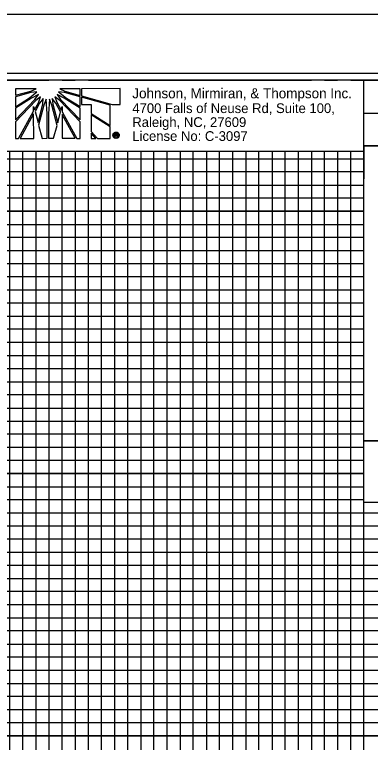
# Model space of a CAD drawing. Extents: x 1648435 to 1651603, y 802691 to 845762.
# Drawn here: x 1650196.2 to 1650331.8, y 803513.5 to 803791 of the extents above; entities that cross this region are included whole.
import ezdxf

# ---------------------------------------------------------------- set-up
doc = ezdxf.new("R2010")
doc.units = 0
for name, color, linetype in [('Prop Dimension Text', 7, 'Continuous'), ('Sheet Cutting Line CELL', 7, 'Continuous'), ('Sheet DOT Grid CELL', 7, 'Continuous'), ('Sheet Plan CELL', 7, 'Continuous'), ('Sheet Plot Border Inside CELL', 7, 'Continuous'), ('Sheet Plot Border Outside CELL', 7, 'Continuous'), ('Sheet Profile CELL', 7, 'Continuous'), ('Sheet Profile Grid Major CELL', 7, 'Continuous'), ('Sheet Profile Grid Middle CELL', 7, 'Continuous'), ('Sheet Profile Grid Minor CELL', 7, 'Continuous'), ('Sheet Sticker Exception Certification CELL', 7, 'Continuous')]:
    doc.layers.add(name, color=color, linetype=linetype)

msp = doc.modelspace()

# ---------------------------------------------------------------- linework, layer by layer
at = {"layer": 'Prop Dimension Text'}
for p, q in [((1650204.41, 803762.75), (1650196.52, 803762.75)), ((1650196.52, 803762.75), (1650196.52, 803760.23)), ((1650202.4, 803761.86), (1650204.41, 803762.75)), ((1650221.14, 803762.73), (1650213.35, 803762.76)), ((1650213.35, 803762.76), (1650215.32, 803761.84)), ((1650221.14, 803760.21), (1650221.14, 803762.73)), ((1650236.43, 803762.78), (1650221.68, 803762.77)), ((1650221.68, 803762.77), (1650221.68, 803760.06)), ((1650236.44, 803756.74), (1650236.43, 803762.78)), ((1650196.52, 803760.23), (1650202.4, 803761.86)), ((1650202.4, 803761.31), (1650196.52, 803759.69)), ((1650196.52, 803759.69), (1650196.52, 803755.89)), ((1650201.79, 803759.23), (1650204.69, 803761.59)), ((1650204.69, 803761.59), (1650202.4, 803761.31)), ((1650205.27, 803760.51), (1650202.6, 803759.15)), ((1650203.92, 803758.61), (1650205.27, 803760.51)), ((1650206.08, 803759.66), (1650204.22, 803758.22)), ((1650205.23, 803757.42), (1650206.08, 803759.66)), ((1650211.53, 803759.67), (1650212.39, 803757.42)), ((1650213.39, 803758.23), (1650211.53, 803759.67)), ((1650212.35, 803760.51), (1650213.71, 803758.58)), ((1650215.06, 803759.16), (1650212.35, 803760.51)), ((1650212.96, 803761.6), (1650215.9, 803759.2)), ((1650215.13, 803761.33), (1650212.96, 803761.6)), ((1650221.14, 803759.68), (1650215.13, 803761.33)), ((1650215.32, 803761.84), (1650221.14, 803760.21)), ((1650221.1, 803755.96), (1650221.14, 803759.68)), ((1650221.68, 803760.06), (1650221.68, 803759.98)), ((1650221.68, 803759.98), (1650233.3, 803756.74)), ((1650221.68, 803759.56), (1650221.68, 803759.52)), ((1650232.56, 803756.47), (1650221.68, 803759.56)), ((1650221.68, 803759.52), (1650221.69, 803756.69)), ((1650196.52, 803755.89), (1650201.79, 803759.23)), ((1650202.6, 803759.15), (1650196.52, 803755.28)), ((1650196.53, 803750.9), (1650203.92, 803758.61)), ((1650204.22, 803758.22), (1650196.53, 803750.16)), ((1650203.76, 803754.74), (1650205.23, 803757.42)), ((1650205.7, 803757.25), (1650203.96, 803754.08)), ((1650205.09, 803749.87), (1650206.9, 803756.87)), ((1650207.09, 803759.04), (1650205.7, 803757.25)), ((1650206.9, 803756.87), (1650207.09, 803759.04)), ((1650208.25, 803758.73), (1650207.29, 803756.48)), ((1650208.56, 803753.19), (1650208.25, 803758.73)), ((1650209.41, 803758.73), (1650209.05, 803753.19)), ((1650210.34, 803756.48), (1650209.41, 803758.73)), ((1650210.53, 803759.04), (1650210.77, 803756.8)), ((1650211.89, 803757.26), (1650210.53, 803759.04)), ((1650210.77, 803756.8), (1650212.59, 803749.71)), ((1650213.71, 803753.97), (1650211.89, 803757.26)), ((1650212.39, 803757.42), (1650213.89, 803754.63)), ((1650221.1, 803750.11), (1650213.39, 803758.23)), ((1650213.71, 803758.58), (1650221.1, 803750.84)), ((1650221.1, 803755.33), (1650215.06, 803759.16)), ((1650215.9, 803759.2), (1650221.1, 803755.96)), ((1650221.69, 803756.69), (1650225.29, 803756.69)), ((1650225.29, 803756.69), (1650225.29, 803753.32)), ((1650233.3, 803756.74), (1650236.44, 803756.74)), ((1650196.52, 803755.28), (1650196.53, 803750.9)), ((1650197.69, 803743.79), (1650203.41, 803754.16)), ((1650203.41, 803754.16), (1650203.41, 803756.01)), ((1650203.41, 803756.01), (1650203.76, 803754.74)), ((1650203.96, 803754.08), (1650205.09, 803749.87)), ((1650207.29, 803756.48), (1650205.32, 803748.89)), ((1650212.36, 803748.78), (1650210.34, 803756.48)), ((1650212.59, 803749.71), (1650213.71, 803753.97)), ((1650213.89, 803754.63), (1650214.25, 803756.02)), ((1650214.25, 803756.02), (1650214.25, 803753.97)), ((1650214.25, 803753.97), (1650219.87, 803743.81)), ((1650221.1, 803750.84), (1650221.1, 803755.33)), ((1650232.57, 803748.72), (1650232.56, 803756.47)), ((1650203.42, 803753.15), (1650198.24, 803743.79)), ((1650203.47, 803743.8), (1650203.42, 803753.15)), ((1650208.57, 803743.84), (1650208.56, 803753.19)), ((1650209.05, 803753.19), (1650209.06, 803743.84)), ((1650219.29, 803743.85), (1650214.25, 803752.97)), ((1650214.25, 803752.97), (1650214.26, 803743.84)), ((1650225.29, 803753.32), (1650232.57, 803748.72)), ((1650225.29, 803752.74), (1650225.3, 803746.47)), ((1650232.57, 803748.18), (1650225.29, 803752.74)), ((1650196.53, 803750.16), (1650196.53, 803743.79)), ((1650205.32, 803748.89), (1650206.64, 803743.83)), ((1650211.01, 803743.84), (1650212.36, 803748.78)), ((1650221.11, 803743.81), (1650221.1, 803750.11)), ((1650225.3, 803746.47), (1650227.81, 803743.82)), ((1650227.12, 803743.82), (1650225.3, 803745.78)), ((1650225.3, 803745.78), (1650225.3, 803743.82)), ((1650232.57, 803743.82), (1650232.57, 803748.18)), ((1650234.42, 803744.49), (1650234.42, 803745.56)), ((1650234.42, 803745.56), (1650234.86, 803745.56)), ((1650234.86, 803746.19), (1650234.86, 803745.97)), ((1650234.86, 803745.97), (1650234.86, 803746.19)), ((1650234.86, 803745.56), (1650234.86, 803745.36)), ((1650234.86, 803745.36), (1650234.86, 803745.56)), ((1650234.86, 803745.56), (1650234.92, 803745.56)), ((1650196.53, 803743.79), (1650197.69, 803743.79)), ((1650198.24, 803743.79), (1650203.47, 803743.8)), ((1650206.64, 803743.83), (1650208.57, 803743.84)), ((1650209.06, 803743.84), (1650211.01, 803743.84)), ((1650214.26, 803743.84), (1650219.29, 803743.85)), ((1650219.87, 803743.81), (1650221.11, 803743.81)), ((1650225.3, 803743.82), (1650227.12, 803743.82)), ((1650227.81, 803743.82), (1650232.57, 803743.82)), ((1650234.66, 803744.49), (1650234.42, 803744.49)), ((1650234.86, 803745.36), (1650234.66, 803745.36)), ((1650234.66, 803745.36), (1650234.66, 803745.1)), ((1650234.66, 803745.1), (1650234.86, 803745.1)), ((1650234.86, 803744.91), (1650234.66, 803744.91)), ((1650234.66, 803744.91), (1650234.66, 803744.49)), ((1650234.89, 803745.36), (1650234.86, 803745.36)), ((1650234.86, 803745.1), (1650234.86, 803744.91)), ((1650234.86, 803744.91), (1650234.86, 803745.1)), ((1650234.86, 803745.1), (1650234.87, 803745.1)), ((1650234.87, 803744.91), (1650234.86, 803744.91)), ((1650234.86, 803744.07), (1650234.86, 803743.83)), ((1650234.86, 803743.83), (1650234.86, 803744.07)), ((1650234.86, 803744.07), (1650234.87, 803744.07)), ((1650234.87, 803743.83), (1650234.86, 803743.83))]:
    msp.add_line(p, q, dxfattribs=at)
msp.add_lwpolyline([(1650179.28, 803738.96), (1650329.23, 803738.96), (1650329.23, 803766.02), (1650179.28, 803766.02)], close=True, dxfattribs=at)
for points in [[(1650202.4, 803761.86), (1650204.41, 803762.75), (1650196.52, 803762.75), (1650196.52, 803760.23), (1650202.4, 803761.86)], [(1650215.32, 803761.84), (1650221.14, 803760.21), (1650221.14, 803762.73), (1650213.35, 803762.76), (1650215.32, 803761.84)], [(1650236.43, 803762.78), (1650221.68, 803762.77), (1650221.68, 803760.06), (1650221.68, 803759.98), (1650233.3, 803756.74), (1650236.44, 803756.74), (1650236.43, 803762.78)], [(1650196.52, 803759.69), (1650196.52, 803755.89), (1650201.79, 803759.23), (1650204.69, 803761.59), (1650202.4, 803761.31), (1650196.52, 803759.69)], [(1650196.52, 803755.28), (1650196.53, 803750.9), (1650203.92, 803758.61), (1650205.27, 803760.51), (1650202.6, 803759.15), (1650196.52, 803755.28)], [(1650206.08, 803759.66), (1650204.22, 803758.22), (1650196.53, 803750.16), (1650196.53, 803743.79), (1650197.69, 803743.79), (1650203.41, 803754.16), (1650203.41, 803756.01), (1650203.76, 803754.74), (1650205.23, 803757.42), (1650206.08, 803759.66)], [(1650211.53, 803759.67), (1650212.39, 803757.42), (1650213.89, 803754.63), (1650214.25, 803756.02), (1650214.25, 803753.97), (1650219.87, 803743.81), (1650221.11, 803743.81), (1650221.1, 803750.11), (1650213.39, 803758.23), (1650211.53, 803759.67)], [(1650212.35, 803760.51), (1650213.71, 803758.58), (1650221.1, 803750.84), (1650221.1, 803755.33), (1650215.06, 803759.16), (1650212.35, 803760.51)], [(1650212.96, 803761.6), (1650215.9, 803759.2), (1650221.1, 803755.96), (1650221.14, 803759.68), (1650215.13, 803761.33), (1650212.96, 803761.6)], [(1650221.68, 803759.56), (1650221.68, 803759.52), (1650221.69, 803756.69), (1650225.29, 803756.69), (1650225.29, 803753.32), (1650232.57, 803748.72), (1650232.56, 803756.47), (1650221.68, 803759.56)], [(1650207.09, 803759.04), (1650205.7, 803757.25), (1650203.96, 803754.08), (1650205.09, 803749.87), (1650206.9, 803756.87), (1650207.09, 803759.04)], [(1650207.29, 803756.48), (1650205.32, 803748.89), (1650206.64, 803743.83), (1650208.57, 803743.84), (1650208.56, 803753.19), (1650208.25, 803758.73), (1650207.29, 803756.48)], [(1650209.41, 803758.73), (1650209.05, 803753.19), (1650209.06, 803743.84), (1650211.01, 803743.84), (1650212.36, 803748.78), (1650210.34, 803756.48), (1650209.41, 803758.73)], [(1650210.53, 803759.04), (1650210.77, 803756.8), (1650212.59, 803749.71), (1650213.71, 803753.97), (1650211.89, 803757.26), (1650210.53, 803759.04)], [(1650198.24, 803743.79), (1650203.47, 803743.8), (1650203.42, 803753.15), (1650198.24, 803743.79)], [(1650214.26, 803743.84), (1650219.29, 803743.85), (1650214.25, 803752.97), (1650214.26, 803743.84)], [(1650225.29, 803752.74), (1650225.3, 803746.47), (1650227.81, 803743.82), (1650232.57, 803743.82), (1650232.57, 803748.18), (1650225.29, 803752.74), (1650225.29, 803752.74)], [(1650225.3, 803743.82), (1650225.3, 803743.82), (1650227.12, 803743.82), (1650225.3, 803745.78), (1650225.3, 803743.82)], [(1650235.33, 803744.74), (1650235.33, 803744.68), (1650235.33, 803744.64), (1650235.33, 803744.61), (1650235.36, 803744.49), (1650235.14, 803744.49)]]:
    msp.add_lwpolyline(points, dxfattribs=at)
for points, degree in [([(1650234.86, 803743.83), (1650234.54, 803743.83), (1650234.25, 803743.95), (1650234.02, 803744.18), (1650233.78, 803744.41), (1650233.67, 803744.69), (1650233.67, 803745.02), (1650233.67, 803745.35), (1650233.78, 803745.64), (1650234.02, 803745.85), (1650234.25, 803746.08), (1650234.52, 803746.19), (1650234.86, 803746.19)], 3), ([(1650234.86, 803745.97), (1650234.59, 803745.97), (1650234.37, 803745.88), (1650234.18, 803745.71), (1650234, 803745.52), (1650233.9, 803745.29), (1650233.9, 803745.02), (1650233.9, 803744.76), (1650234, 803744.53), (1650234.18, 803744.34), (1650234.37, 803744.16), (1650234.59, 803744.07), (1650234.86, 803744.07)], 3), ([(1650234.86, 803746.19), (1650235.19, 803746.19), (1650235.47, 803746.08), (1650235.7, 803745.85), (1650235.94, 803745.64), (1650236.06, 803745.36), (1650236.06, 803745.03)], 3), ([(1650234.87, 803744.07), (1650235.13, 803744.07), (1650235.35, 803744.16), (1650235.54, 803744.34), (1650235.72, 803744.53), (1650235.82, 803744.76), (1650235.82, 803745.03), (1650235.82, 803745.29), (1650235.72, 803745.52), (1650235.54, 803745.71), (1650235.35, 803745.88), (1650235.13, 803745.97), (1650234.86, 803745.97)], 3), ([(1650234.92, 803745.56), (1650235.2, 803745.56), (1650235.33, 803745.45), (1650235.33, 803745.24), (1650235.33, 803745.14), (1650235.3, 803745.06), (1650235.21, 803745)], 3), ([(1650234.87, 803745.1), (1650235.02, 803745.1), (1650235.1, 803745.15), (1650235.1, 803745.24), (1650235.1, 803745.32), (1650235.03, 803745.36), (1650234.89, 803745.36)], 3), ([(1650236.06, 803745.03), (1650236.06, 803744.69), (1650235.94, 803744.41), (1650235.72, 803744.18), (1650235.48, 803743.95), (1650235.2, 803743.83), (1650234.87, 803743.83)], 3), ([(1650235.05, 803744.87), (1650235.02, 803744.89), (1650234.96, 803744.91), (1650234.87, 803744.91)], 2), ([(1650235.14, 803744.49), (1650235.11, 803744.55), (1650235.09, 803744.61), (1650235.09, 803744.68), (1650235.09, 803744.78), (1650235.08, 803744.84), (1650235.05, 803744.87)], 3), ([(1650235.21, 803745), (1650235.28, 803744.97), (1650235.32, 803744.88), (1650235.33, 803744.74)], 2)]:
    msp.add_open_spline(points, degree=degree, dxfattribs=at)
at = {"layer": 'Sheet Cutting Line CELL'}
msp.add_line((1650546.28, 803791.02), (1648862.28, 803791.02), dxfattribs=at)
at = {"layer": 'Sheet DOT Grid CELL'}
for p, q in [((1650229.28, 803266.02), (1650229.28, 803718.48)), ((1650279.28, 803266.02), (1650279.28, 803718.48)), ((1650329.23, 803716.02), (1649029.28, 803716.02)), ((1650329.23, 803666.02), (1649029.28, 803666.02)), ((1650329.28, 803266.02), (1650329.28, 803628.47)), ((1650329.28, 803616.02), (1649029.28, 803616.02)), ((1650529.28, 803566.02), (1649029.28, 803566.02)), ((1650529.28, 803516.02), (1649029.28, 803516.02))]:
    msp.add_line(p, q, dxfattribs=at)
at = {"layer": 'Sheet Plan CELL'}
msp.add_line((1650329.23, 803740.94), (1650329.23, 803728.45), dxfattribs=at)
msp.add_line((1650329.23, 803740.94), (1650329.23, 803728.45), dxfattribs=at)
msp.add_line((1650329.23, 803740.94), (1650329.23, 803728.45), dxfattribs=at)
at = {"layer": 'Sheet Plot Border Inside CELL'}
msp.add_lwpolyline([(1648875.28, 802713.47), (1650541.78, 802713.47), (1650541.78, 803768.57), (1648875.28, 803768.57)], close=True, dxfattribs=at)
at = {"layer": 'Sheet Plot Border Outside CELL'}
msp.add_lwpolyline([(1648862.28, 802691.02), (1650546.28, 802691.02), (1650546.28, 803791.02), (1648862.28, 803791.02)], close=True, dxfattribs=at)
at = {"layer": 'Sheet Profile CELL'}
msp.add_line((1650329.23, 803753.47), (1650529.28, 803753.47), dxfattribs=at)
for points in [[(1650529.28, 803766.02), (1649029.28, 803766.02), (1649029.28, 802716.02), (1650529.28, 802716.02)], [(1650329.23, 803766.02), (1650529.28, 803766.02), (1650529.28, 803740.97), (1650329.23, 803740.97)], [(1650329.23, 803740.97), (1650429.28, 803740.97), (1650429.28, 803628.47), (1650329.23, 803628.47)]]:
    msp.add_lwpolyline(points, close=True, dxfattribs=at)
at = {"layer": 'Sheet Profile Grid Major CELL'}
for points in [[(1650029.28, 803766.02), (1650079.28, 803766.02), (1650079.28, 803266.02), (1650129.28, 803266.02), (1650129.28, 803766.02), (1650179.28, 803766.02), (1650179.28, 803266.02), (1650229.28, 803266.02), (1650229.28, 803738.96)], [(1650229.28, 803766.02), (1650279.28, 803766.02)], [(1650279.23, 803738.96), (1650279.23, 803266.02), (1650329.23, 803266.02), (1650329.23, 803766.02), (1650355.53, 803766.02)], [(1649029.28, 803716.02), (1650329.28, 803716.02)], [(1650329.28, 803666.02), (1649029.28, 803666.02), (1649029.28, 803616.02), (1650329.28, 803616.02)], [(1650529.28, 803566.02), (1649029.28, 803566.02), (1649029.28, 803516.02), (1650529.28, 803516.02)]]:
    msp.add_lwpolyline(points, dxfattribs=at)
at = {"layer": 'Sheet Profile Grid Middle CELL'}
for points in [[(1650004.28, 803266.02), (1650054.28, 803266.02), (1650054.28, 803766.02), (1650104.28, 803766.02), (1650104.28, 803266.02), (1650154.28, 803266.02), (1650154.28, 803766.02), (1650204.28, 803766.02)], [(1650254.28, 803766.02), (1650304.28, 803766.02)], [(1650204.28, 803738.96), (1650204.28, 803266.02), (1650254.28, 803266.02), (1650254.28, 803738.96)], [(1650304.28, 803738.96), (1650304.28, 803266.02), (1650354.28, 803266.02), (1650354.28, 803604.97)], [(1650329.28, 803691.02), (1649029.28, 803691.02), (1649029.28, 803641.02), (1650329.28, 803641.02)], [(1650529.28, 803591.02), (1649029.28, 803591.02), (1649029.28, 803541.02), (1650354.28, 803541.02)]]:
    msp.add_lwpolyline(points, dxfattribs=at)
at = {"layer": 'Sheet Profile Grid Minor CELL'}
for p, q in [((1650329.23, 803761.02), (1650329.28, 803761.02)), ((1650329.28, 803756.02), (1650329.23, 803756.02)), ((1650329.23, 803751.02), (1650329.28, 803751.02)), ((1650329.23, 803631.02), (1649079.28, 803631.02)), ((1650329.28, 803626.02), (1649079.28, 803626.02)), ((1650329.28, 803621.02), (1649079.28, 803621.02)), ((1649079.28, 803611.02), (1650329.28, 803611.02)), ((1650329.28, 803606.02), (1649079.28, 803606.02)), ((1649079.28, 803601.02), (1650479.28, 803601.02)), ((1650479.28, 803581.02), (1649079.28, 803581.02)), ((1649079.28, 803576.02), (1650479.28, 803576.02)), ((1650479.28, 803556.02), (1649079.28, 803556.02)), ((1649079.28, 803551.02), (1650479.28, 803551.02)), ((1650479.28, 803531.02), (1649079.28, 803531.02)), ((1649079.28, 803526.02), (1650479.28, 803526.02)), ((1650479.28, 803521.02), (1649079.28, 803521.02))]:
    msp.add_line(p, q, dxfattribs=at)
for points in [[(1650199.28, 803766.02), (1650209.28, 803766.02)], [(1650214.28, 803766.02), (1650219.28, 803766.02)], [(1650224.28, 803766.02), (1650234.28, 803766.02)], [(1650239.28, 803766.02), (1650244.28, 803766.02)], [(1650249.28, 803766.02), (1650259.28, 803766.02)], [(1650264.28, 803766.02), (1650269.28, 803766.02)], [(1650274.28, 803766.02), (1650284.28, 803766.02)], [(1650289.28, 803766.02), (1650294.28, 803766.02)], [(1650299.28, 803766.02), (1650309.28, 803766.02)], [(1650314.28, 803766.02), (1650319.28, 803766.02)], [(1650324.28, 803766.02), (1650334.28, 803766.02)], [(1650179.28, 803746.02), (1649079.28, 803746.02), (1649079.28, 803736.02), (1650329.28, 803736.02)], [(1650329.28, 803746.02), (1650329.23, 803746.02)], [(1650194.28, 803738.96), (1650194.28, 803266.02), (1650199.28, 803266.02), (1650199.28, 803738.96)], [(1650209.28, 803738.96), (1650209.28, 803266.02), (1650214.28, 803266.02), (1650214.28, 803738.96)], [(1650219.28, 803266.02), (1650224.28, 803266.02), (1650224.28, 803738.96)], [(1650219.28, 803738.96), (1650219.28, 803266.02)], [(1650234.28, 803738.96), (1650234.28, 803266.02), (1650239.28, 803266.02), (1650239.28, 803738.96)], [(1650244.28, 803738.96), (1650244.28, 803266.02), (1650249.28, 803266.02), (1650249.28, 803738.96)], [(1650259.28, 803738.96), (1650259.28, 803266.02), (1650264.28, 803266.02), (1650264.28, 803738.96)], [(1650269.28, 803738.96), (1650269.28, 803266.02), (1650274.28, 803266.02), (1650274.28, 803738.96)], [(1650284.28, 803738.96), (1650284.28, 803266.02), (1650289.28, 803266.02), (1650289.28, 803738.96)], [(1650294.28, 803738.96), (1650294.28, 803266.02), (1650299.28, 803266.02), (1650299.28, 803738.96)], [(1650309.28, 803738.96), (1650309.28, 803266.02), (1650314.28, 803266.02), (1650314.28, 803738.96)], [(1650319.28, 803738.96), (1650319.28, 803266.02), (1650324.28, 803266.02), (1650324.28, 803738.96)], [(1650329.23, 803731.02), (1649079.28, 803731.02), (1649079.28, 803726.02), (1650329.28, 803726.02)], [(1650329.28, 803721.02), (1649079.28, 803721.02), (1649079.28, 803711.02), (1650329.28, 803711.02)], [(1650329.28, 803706.02), (1649079.28, 803706.02), (1649079.28, 803701.02), (1650329.28, 803701.02)], [(1650329.28, 803696.02), (1649079.28, 803696.02), (1649079.28, 803686.02), (1650329.28, 803686.02)], [(1650329.28, 803681.02), (1649079.28, 803681.02), (1649079.28, 803676.02), (1650329.28, 803676.02)], [(1650329.28, 803671.02), (1649079.28, 803671.02), (1649079.28, 803661.02), (1650329.28, 803661.02)], [(1650329.28, 803655.92), (1649079.38, 803655.92), (1649079.38, 803651.02), (1650329.28, 803651.02)], [(1650329.28, 803646.02), (1649079.28, 803646.02), (1649079.28, 803636.02), (1650329.28, 803636.02)], [(1650479.28, 803596.02), (1649079.28, 803596.02), (1649079.28, 803586.02), (1650479.28, 803586.02)], [(1650479.28, 803571.02), (1649079.28, 803571.02), (1649079.28, 803561.02), (1650479.28, 803561.02)], [(1650479.28, 803546.02), (1649079.28, 803546.02), (1649079.28, 803536.02), (1650479.28, 803536.02)]]:
    msp.add_lwpolyline(points, dxfattribs=at)
at = {"layer": 'Sheet Sticker Exception Certification CELL'}
for p, q in [((1650329.23, 803604.97), (1650329.23, 803628.47)), ((1650329.23, 803628.47), (1650529.27, 803628.47)), ((1650329.23, 803604.97), (1650329.23, 803628.47)), ((1650329.23, 803628.47), (1650529.27, 803628.47)), ((1650529.27, 803604.97), (1650329.23, 803604.97)), ((1650529.27, 803604.97), (1650329.23, 803604.97))]:
    msp.add_line(p, q, dxfattribs=at)

# ---------------------------------------------------------------- texts
at = {"layer": 'Prop Dimension Text'}
for s, height, p in [('Johnson, Mirmiran, & Thompson Inc.', 3.8315, (1650241.03, 803759.09)), ('4700 Falls of Neuse Rd, Suite 100, ', 3.722, (1650241.03, 803753.47)), ('Raleigh, NC, 27609', 3.722, (1650241.03, 803748.15)), ('License No: C-3097', 3.722, (1650241.03, 803742.83))]:
    msp.add_text(s, height=height, rotation=360, dxfattribs=at).set_placement(p)

doc.saveas('drawing.dxf')
